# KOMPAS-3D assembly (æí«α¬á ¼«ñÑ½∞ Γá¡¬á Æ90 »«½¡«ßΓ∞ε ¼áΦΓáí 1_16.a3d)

Referenced files in D:\АСКОН работа\Конкурс HOME\06_Сюваев_Сборная модель танка Т90\СБОРКИ\СБОРКА КОРПУСА ШТАМПОВКА\: СБОРКА КОРПУС ПОЛНОСТЬЮ.a3d
Referenced files in D:\АСКОН работа\Конкурс HOME\06_Сюваев_Сборная модель танка Т90\ДЕТАЛИ\БАШНЯ\башня сварная\: Сборка башня полностью.a3d
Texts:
  Сборка модель танка т90 сварная башня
